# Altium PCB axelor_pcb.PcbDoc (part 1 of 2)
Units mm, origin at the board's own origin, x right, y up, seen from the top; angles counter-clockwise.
Board outline 74.68 x 44.83 mm, 4 copper layers (Top Layer, Int1 (GND), Int2 (PWR), Bottom Layer), stack 1.586 mm thick; 281 components, 64 nets, 713 pads, 300 vias.
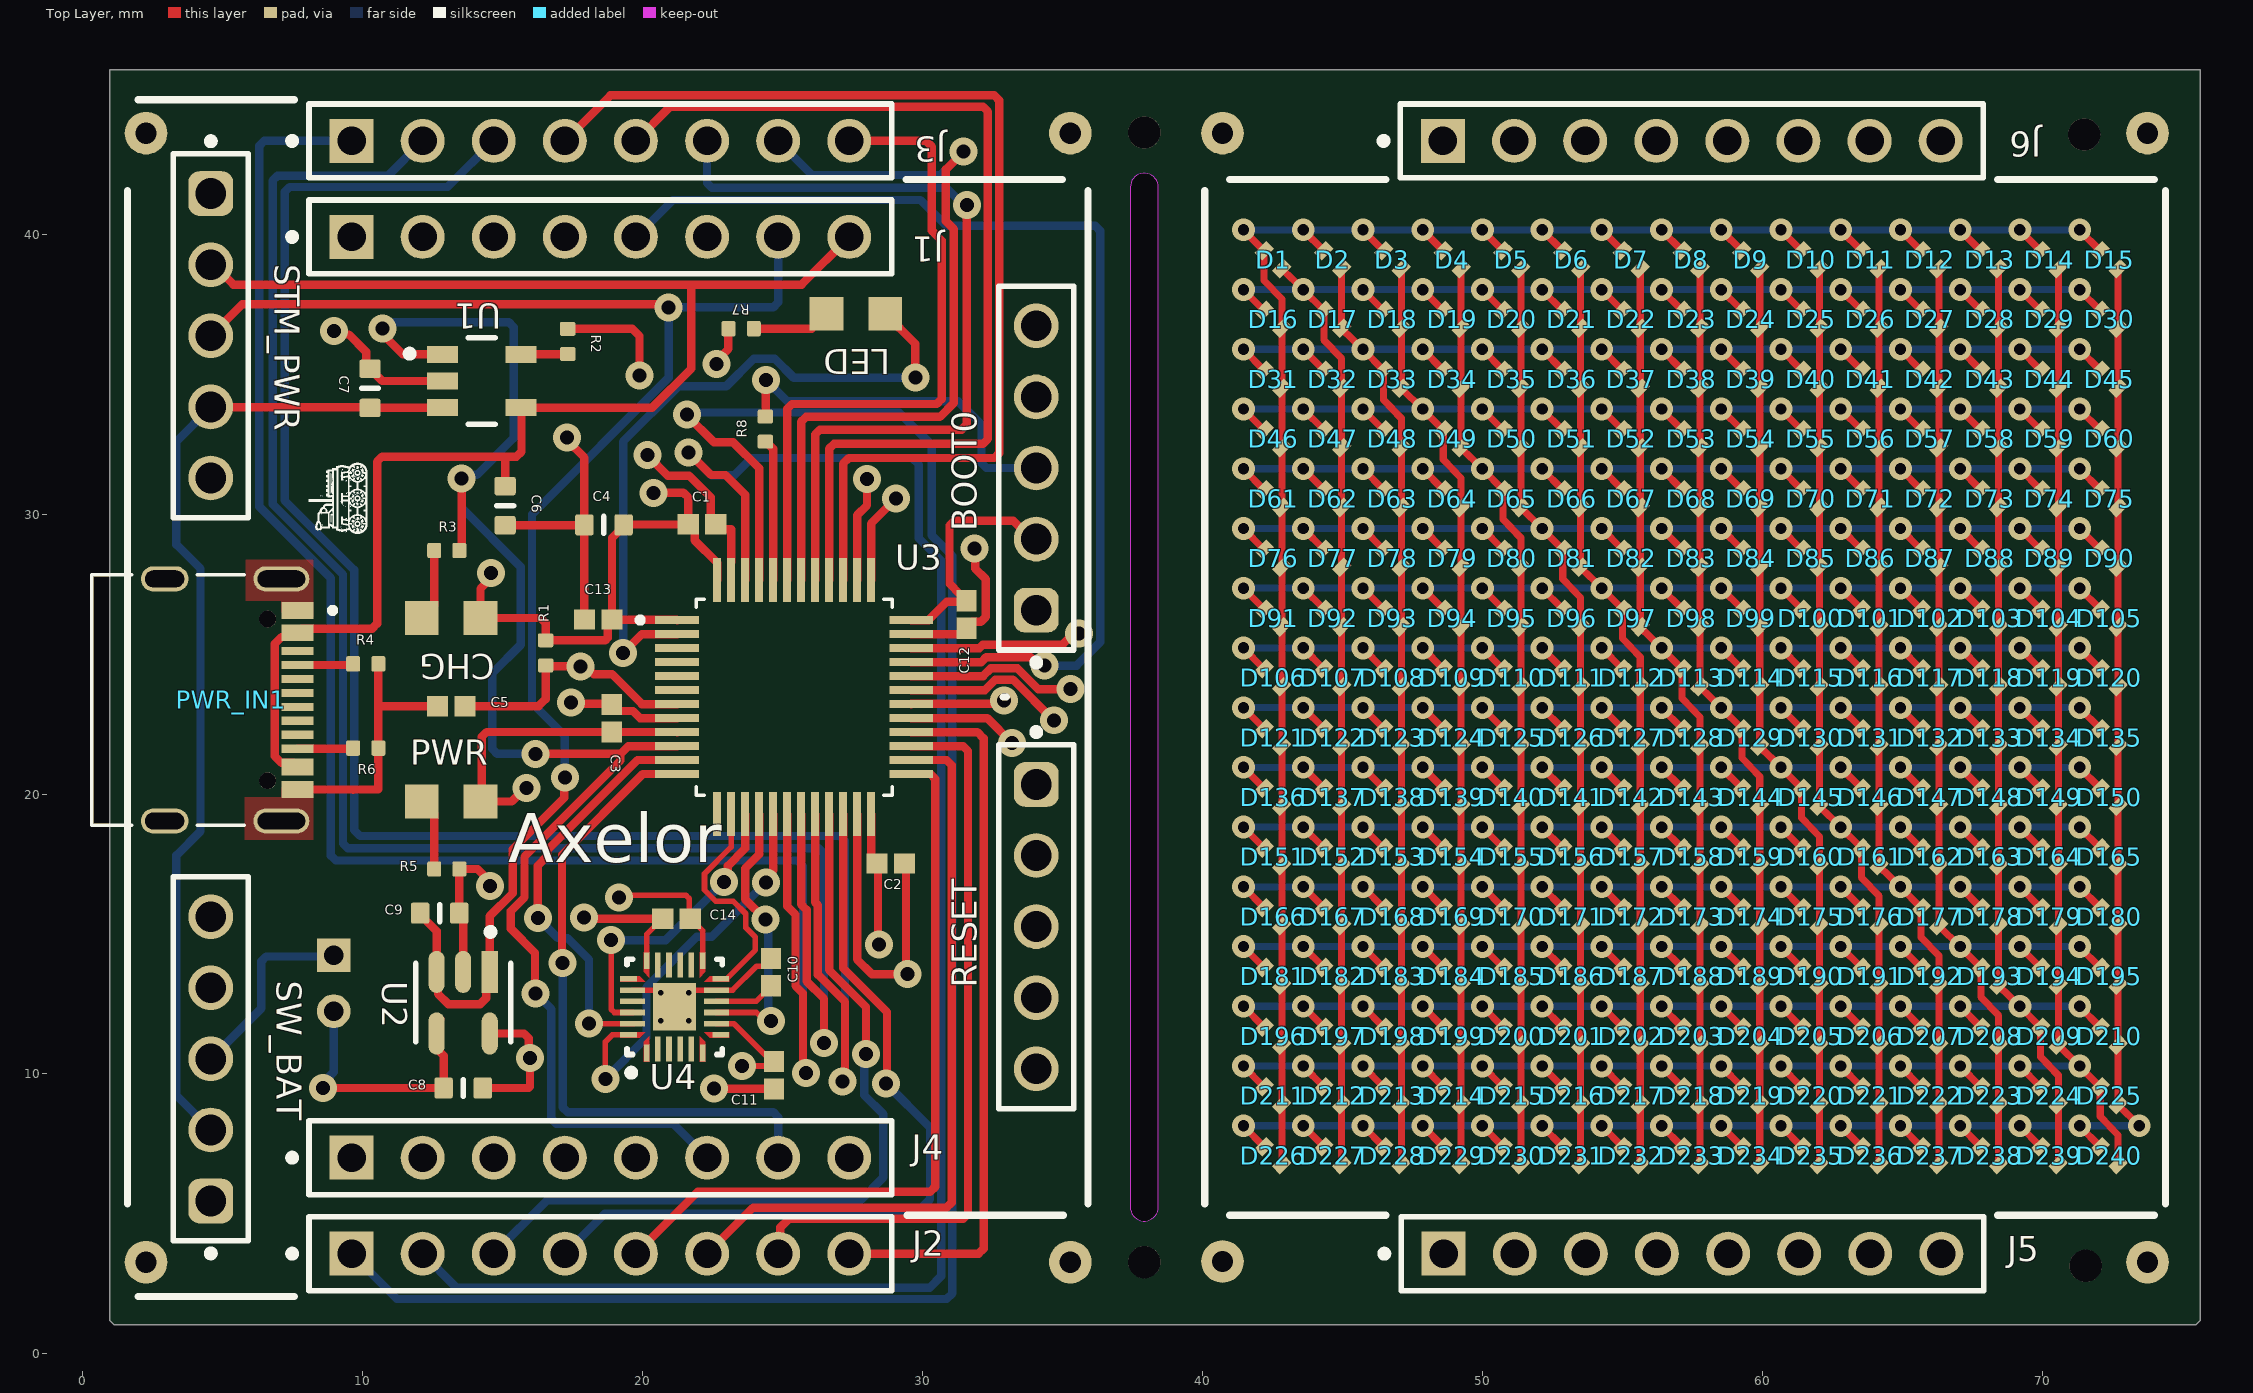
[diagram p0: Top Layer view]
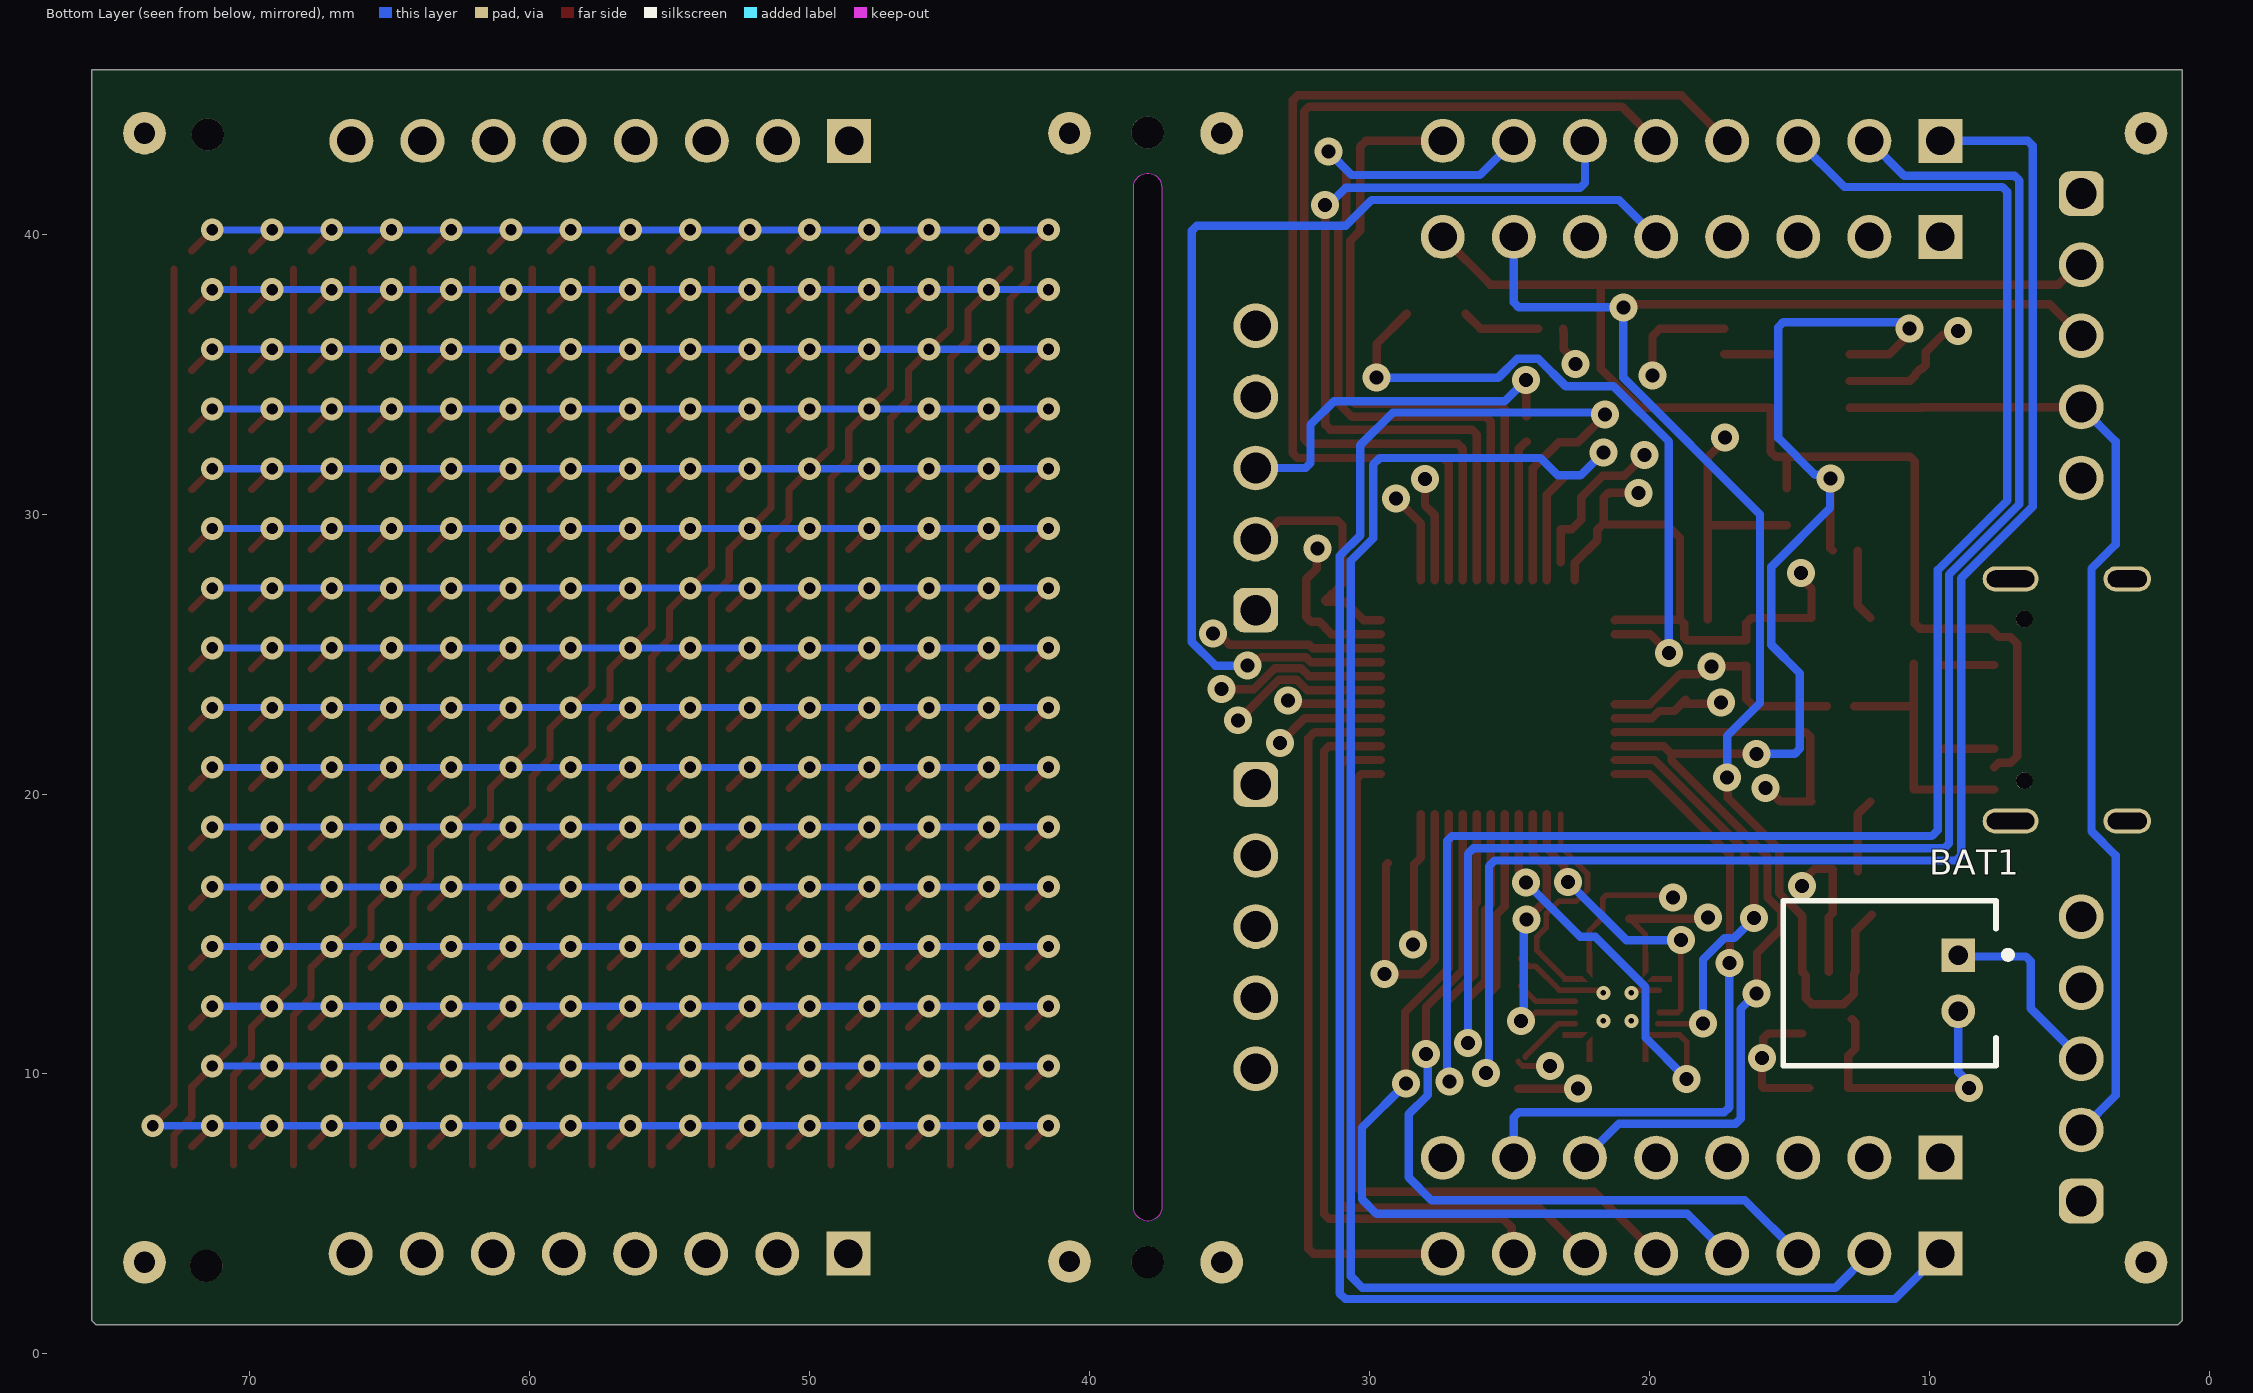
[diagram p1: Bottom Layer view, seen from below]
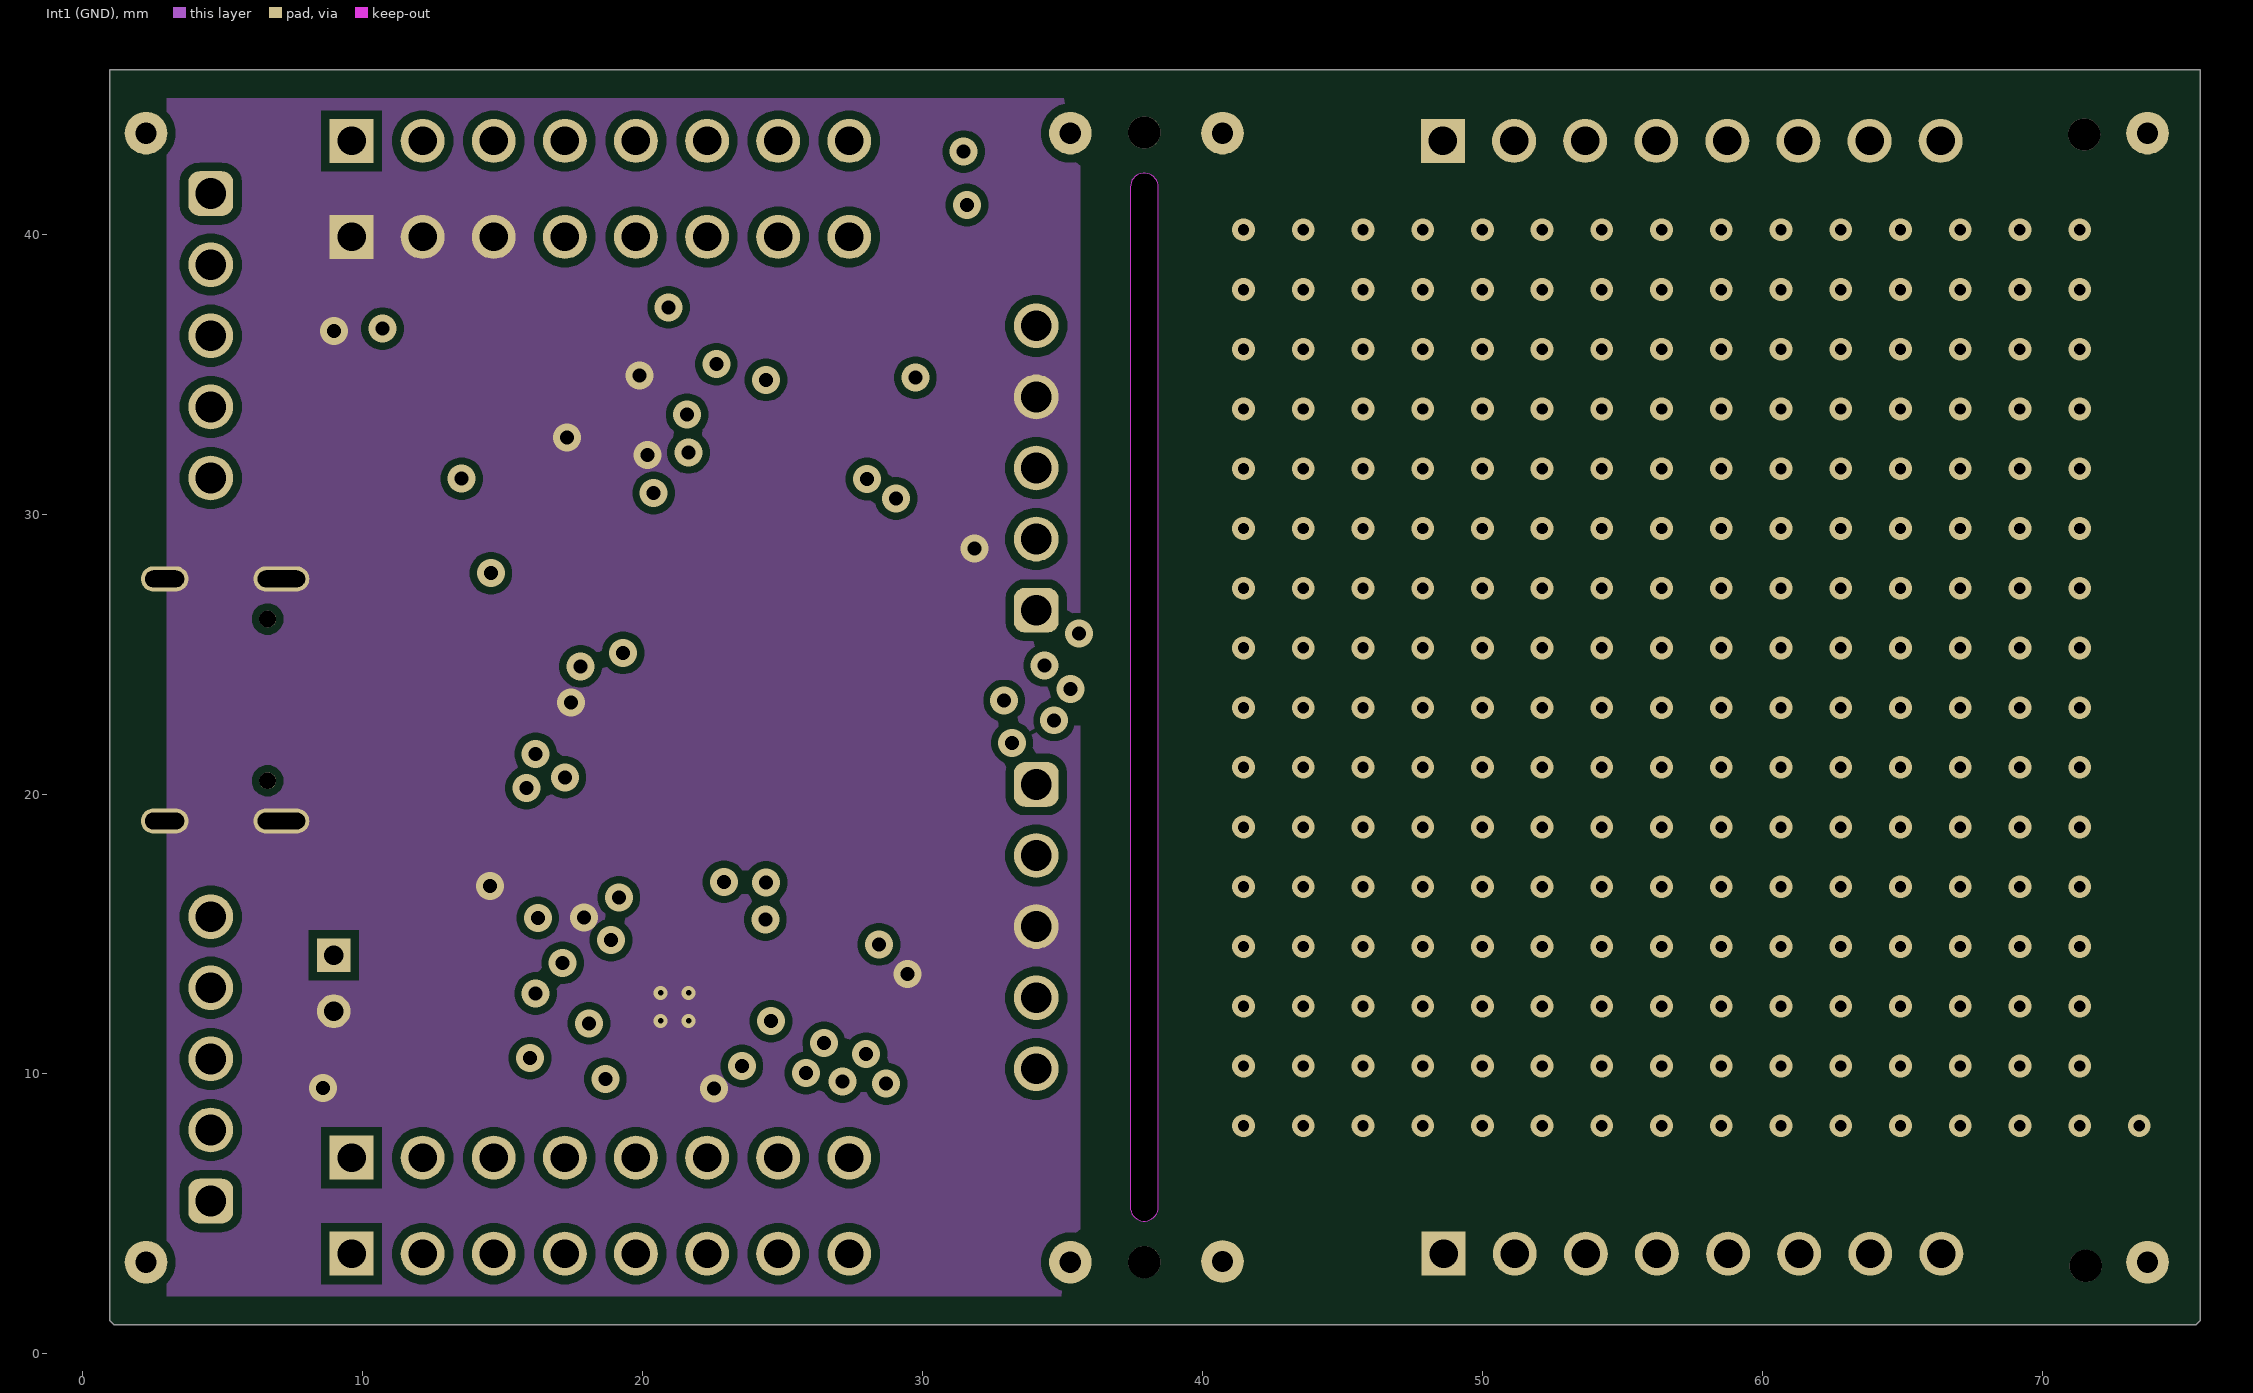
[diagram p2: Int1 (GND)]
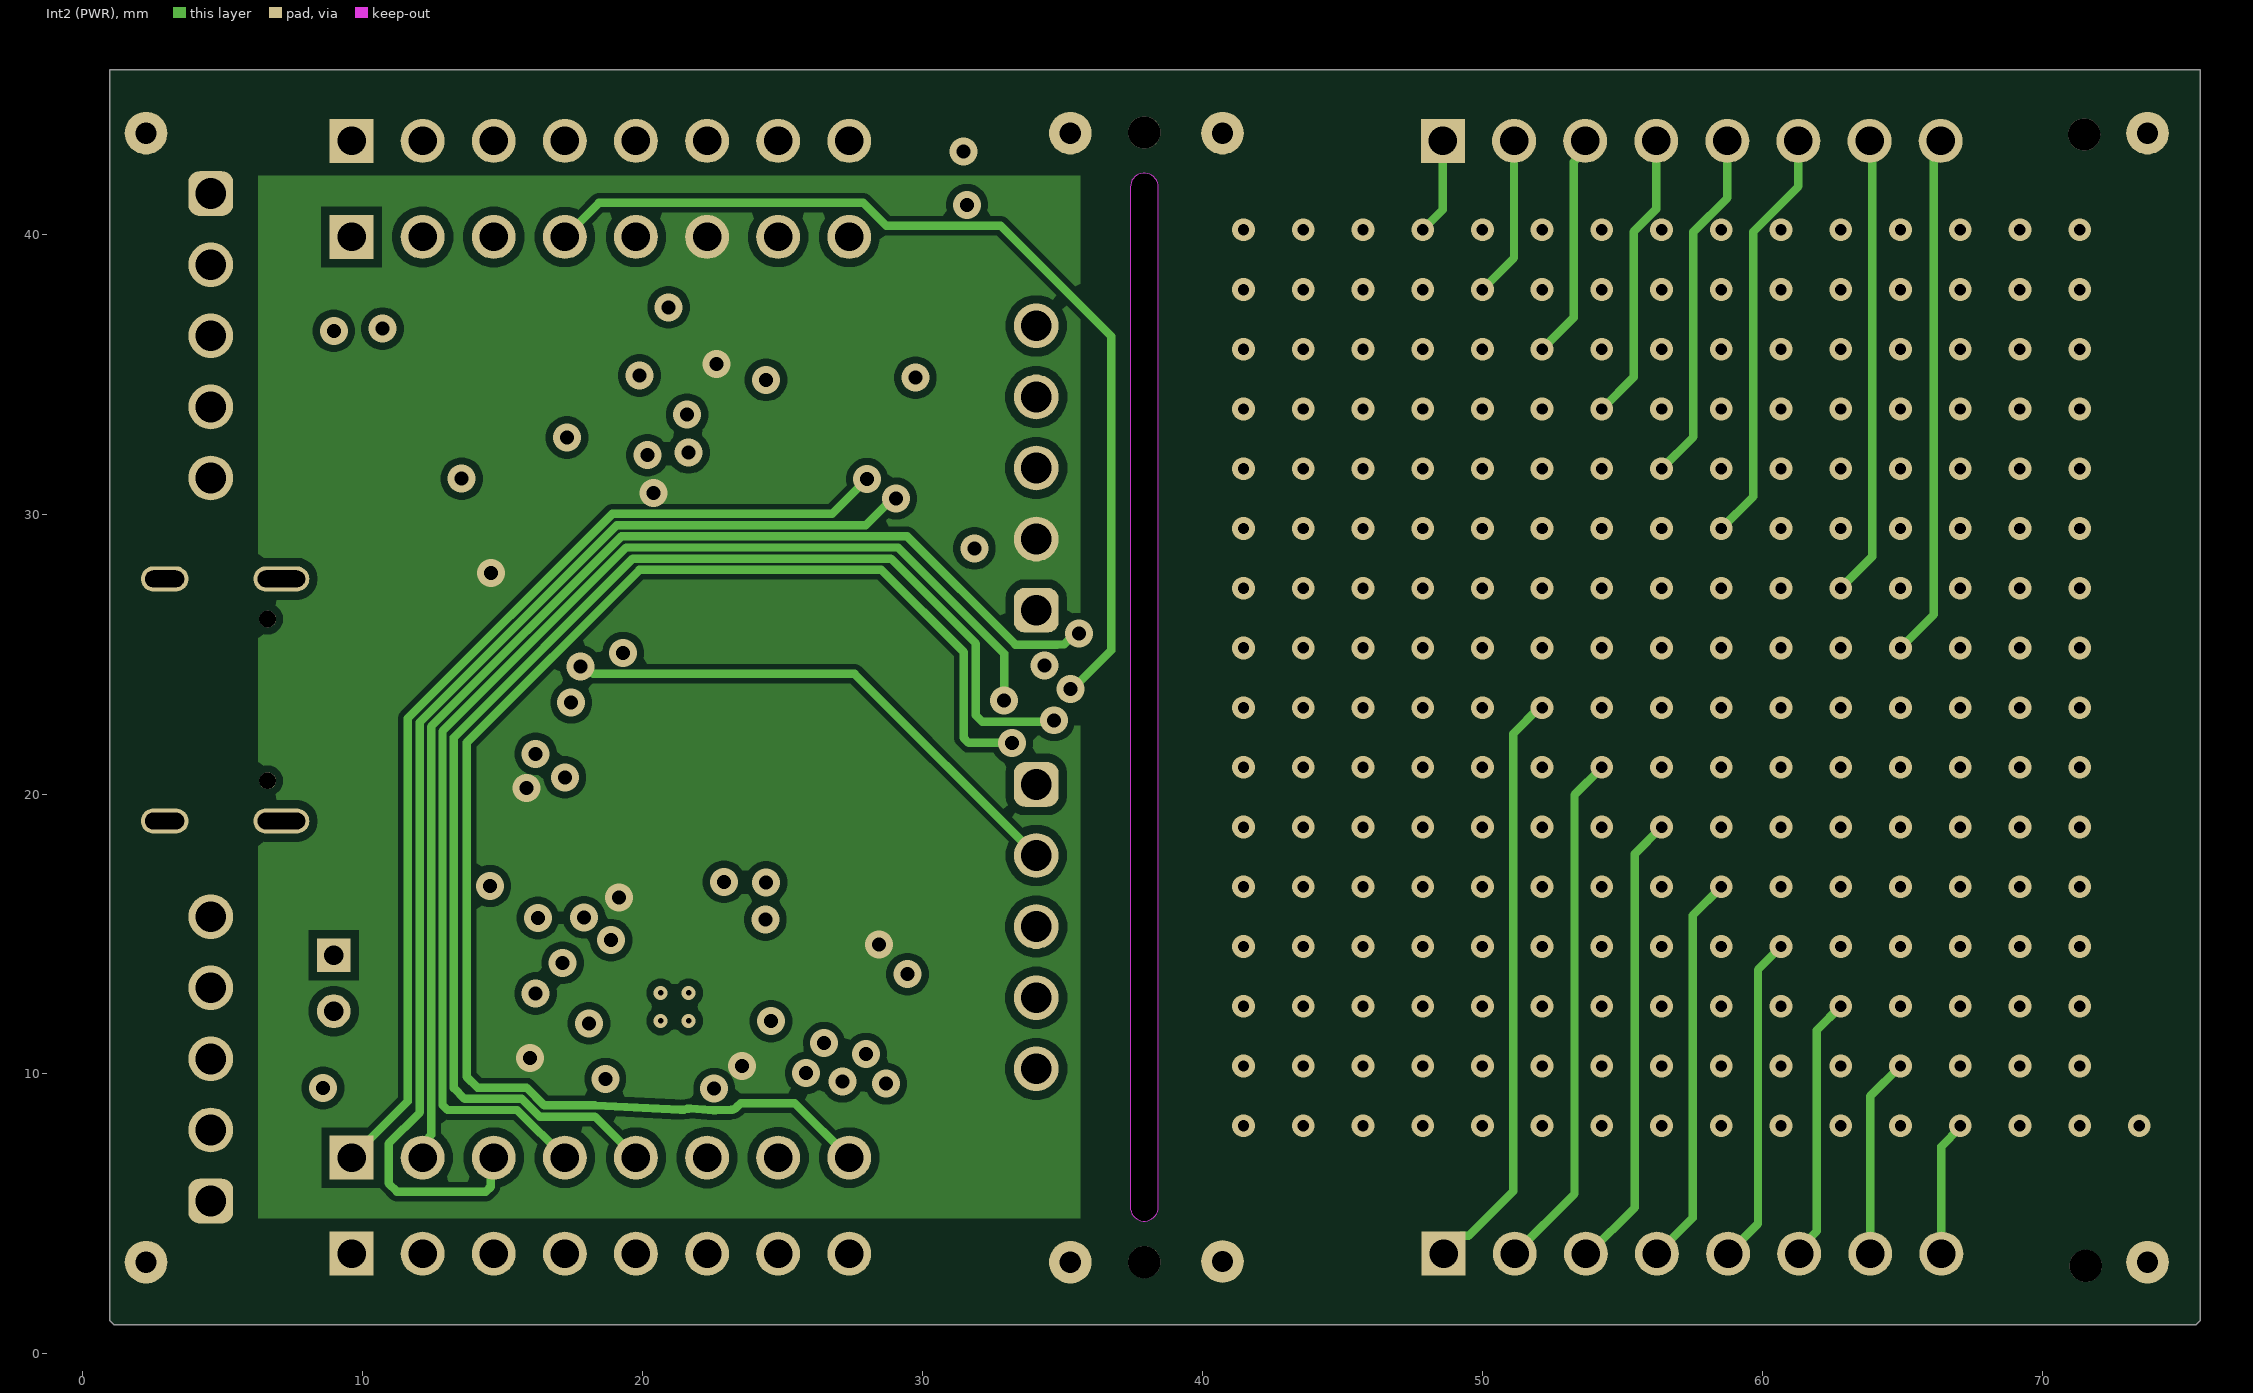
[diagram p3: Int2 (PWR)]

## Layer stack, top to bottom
Top Solder: solder mask 0.0254, SM-001, Dk 4
Top Layer: signal copper 0.035
Dielectric 1: prepreg 0.2104, PP-017, Dk 4.4
Int1 (GND): signal copper 0.0152
Dielectric 3: core 1.065, Core-039, Dk 4.43
Int2 (PWR): signal copper 0.0152
Dielectric 5: prepreg 0.2104, PP-017, Dk 4.4
Bottom Layer: signal copper 0.035
Bottom Solder: solder mask 0.0254, SM-001, Dk 4

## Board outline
0.965,1.19 0.965,45.872 75.641,45.872 75.641,1.19 75.492,1.041 1.114,1.041
cut-out: 37.422,5.243 ccw(c37.922,5.243) 38.422,5.243 38.422,41.681 ccw(c37.922,41.681) 37.422,41.681 37.422,6.51

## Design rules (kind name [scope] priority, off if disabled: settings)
Clearance [All] p1: gap=0.254 ignorepadtopadclearanceinfootprint=FALSE except(0.1: Arc-Arc Arc-Track Arc-SMDPad Arc-Via Track-Track Track-SMDPad Track-Via; 0.15: SMDPad-SMDPad; 0.2: Arc-Fill Arc-Poly Arc-Region Track-Fill Track-Poly Track-Region SMDPad-Fill SMDPad-Poly SMDPad-Region SMDPad-Hole Fill-Fill Fill-Poly Fill-Region Poly-Poly Poly-Region Region-Region; 0.28: Arc-THPad Track-THPad; 0.3: THPad-Fill THPad-Poly THPad-Region)
MinimumSolderMaskSliver [All] p1: minsoldermaskwidth=0.1
PolygonConnect [All] p1: connectstyle=Direct reliefconductorwidth=0.254 reliefentries=4 polygonreliefangle="90 Angle" airgapwidth=0.254
RoutingVias [All] p1: holewidth=0.5 width=1 viastyle="Through Hole" minholewidth=0.15 minwidth=0.25 maxholewidth=0.711 maxwidth=1.27
SolderMaskExpansion [All] p1: expansion=0 istentingtop=FALSE
SupplyNets "Schematic Supply Nets_4" [InNet('VBUS')] p1: voltage=0.000
SupplyNets "Schematic Supply Nets_3" [InNet('VCC3V3')] p2: voltage=0.000
SupplyNets "Schematic Supply Nets_2" [InNet('VBAT')] p3: voltage=0.000
SupplyNets "Schematic Supply Nets_1" [InNet('GND')] p4: voltage=0.000
SupplyNets "Schematic Supply Nets" [InNet('VCC5V')] p5: voltage=0.000
UnRoutedNet [All] p1: checkbadconnections=TRUE
Width [All] p1: maxlimit=1 minlimit=0.2 preferedwidth=0.3
28 further rules are at their usual default settings.

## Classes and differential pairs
component class main_board: BAT1 BOOT0 C1 C2 C3 C4 C5 C6 C7 C8 C9 C10 C11 C12 C13 C14 CHG J1 J2 J3 J4 LED PWR PWR_IN1 R1 R2 R3 R4 R5 R6 R7 R8 RESET STM_PWR SW_BAT U1 U2 U3 U4
component class led_matrix: D1 D2 D3 D4 D5 D6 D7 D8 D9 D10 D11 D12 D13 D14 D15 D16 D17 D18 D19 D20 D21 D22 D23 D24 D25 D26 D27 D28 D29 D30 D31 D32 D33 D34 D35 D36 D37 D38 D39 D40 D41 D42 D43 D44 D45 D46 D47 D48 D49 D50 D51 D52 D53 D54 D55 D56 D57 D58 D59 D60 D61 D62 D63 D64 D65 D66 D67 D68 D69 D70 D71 D72 D73 D74 D75 D76 D77 D78 D79 D80 D81 D82 D83 D84 D85 D86 D87 D88 D89 D90 D91 D92 D93 D94 D95 D96 D97 D98 D99 D100 D101 D102 D103 D104 D105 D106 D107 D108 D109 D110 D111 D112 D113 D114 D115 D116 D117 D118 D119 D120 D121 D122 D123 D124 D125 D126 D127 D128 D129 D130 D131 D132 D133 D134 D135 D136 D137 D138 D139 D140 D141 D142 D143 D144 D145 D146 D147 D148 D149 D150 D151 D152 D153 D154 D155 D156 D157 D158 D159 D160 D161 D162 D163 D164 D165 D166 D167 D168 D169 D170 D171 D172 D173 D174 D175 D176 D177 D178 D179 D180 D181 D182 D183 D184 D185 D186 D187 D188 D189 D190 D191 D192 D193 D194 D195 D196 D197 D198 D199 D200 D201 D202 D203 D204 D205 D206 D207 D208 D209 D210 D211 D212 D213 D214 D215 D216 D217 D218 D219 D220 D221 D222 D223 D224 D225 D226 D227 D228 D229 D230 D231 D232 D233 D234 D235 D236 D237 D238 D239 D240 J5 J6

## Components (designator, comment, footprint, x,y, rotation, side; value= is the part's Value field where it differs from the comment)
BAT1 "S2B-PH-K-S(LF)(SN)" JST-S2B-PH-K-S_V 11.416,13.243 r270 bottom
BOOT0 "61300511121" 61300511121 34.061,31.648 r90 top
C1 "100nF" CAPC1050X55X23ML05T13 22.123,29.642 r180 top
C2 "100nF" CAPC1050X55X23ML05T13 28.862,17.526 r180 top
C3 "100nF" CAPC1050X55X23ML05T13 18.898,22.708 r270 top
C4 "10uF" CAPC0603(1608)100_L 18.618,29.616 r0 top value=4.7µF
C5 "100nF" CAPC1050X55X23ML05T13 13.165,23.139 r0 top
C6 "4u7" CAPC0603(1608)100_L 15.088,30.302 r90 top value=4.7µF
C7 "4u7" CAPC0603(1608)100_L 10.262,34.493 r270 top value=4.7µF
C8 "4u7" CAPC0603(1608)100_L 13.589,9.5 r0 top value=4.7µF
C9 "4u7" CAPC0603(1608)100_L 12.751,15.748 r180 top value=4.7µF
C10 "100nF" CAPC1050X55X23ML05T13 24.587,13.64 r270 top
C11 "100nF" CAPC1050X55X23ML05T13 24.689,9.957 r90 top
C12 "100nF" CAPC1050X55X23ML05T13 31.572,26.416 r90 top
C13 "100nF" CAPC1050X55X23ML05T13 18.415,26.238 r0 top
C14 "100nF" CAPC1050X55X23ML05T13 21.209,15.545 r0 top
CHG "YELLOW_0805" EVRL-17-21SYGC_V 13.157,26.289 r180 top
D1 "LED_MTX" EVRL-0402-2_V 42.52,39.09 r315 top
D2 "LED_MTX" EVRL-0402-2_V 44.654,39.09 r315 top
D3 "LED_MTX" EVRL-0402-2_V 46.787,39.09 r315 top
D4 "LED_MTX" EVRL-0402-2_V 48.921,39.09 r315 top
D5 "LED_MTX" EVRL-0402-2_V 51.055,39.09 r315 top
D6 "LED_MTX" EVRL-0402-2_V 53.188,39.09 r315 top
D7 "LED_MTX" EVRL-0402-2_V 55.322,39.09 r315 top
D8 "LED_MTX" EVRL-0402-2_V 57.455,39.09 r315 top
D9 "LED_MTX" EVRL-0402-2_V 59.589,39.09 r315 top
D10 "LED_MTX" EVRL-0402-2_V 61.723,39.09 r315 top
D11 "LED_MTX" EVRL-0402-2_V 63.856,39.09 r315 top
D12 "LED_MTX" EVRL-0402-2_V 65.99,39.09 r315 top
D13 "LED_MTX" EVRL-0402-2_V 68.123,39.09 r315 top
D14 "LED_MTX" EVRL-0402-2_V 70.257,39.09 r315 top
D15 "LED_MTX" EVRL-0402-2_V 72.391,39.09 r315 top
D16 "LED_MTX" EVRL-0402-2_V 42.52,36.956 r315 top
D17 "LED_MTX" EVRL-0402-2_V 44.654,36.956 r315 top
D18 "LED_MTX" EVRL-0402-2_V 46.787,36.956 r315 top
D19 "LED_MTX" EVRL-0402-2_V 48.921,36.956 r315 top
D20 "LED_MTX" EVRL-0402-2_V 51.055,36.956 r315 top
D21 "LED_MTX" EVRL-0402-2_V 53.188,36.956 r315 top
D22 "LED_MTX" EVRL-0402-2_V 55.322,36.956 r315 top
D23 "LED_MTX" EVRL-0402-2_V 57.455,36.956 r315 top
D24 "LED_MTX" EVRL-0402-2_V 59.589,36.956 r315 top
D25 "LED_MTX" EVRL-0402-2_V 61.723,36.956 r315 top
D26 "LED_MTX" EVRL-0402-2_V 63.856,36.956 r315 top
D27 "LED_MTX" EVRL-0402-2_V 65.99,36.956 r315 top
D28 "LED_MTX" EVRL-0402-2_V 68.123,36.956 r315 top
D29 "LED_MTX" EVRL-0402-2_V 70.257,36.956 r315 top
D30 "LED_MTX" EVRL-0402-2_V 72.391,36.956 r315 top
D31 "LED_MTX" EVRL-0402-2_V 42.52,34.823 r315 top
D32 "LED_MTX" EVRL-0402-2_V 44.654,34.823 r315 top
D33 "LED_MTX" EVRL-0402-2_V 46.787,34.823 r315 top
D34 "LED_MTX" EVRL-0402-2_V 48.921,34.823 r315 top
D35 "LED_MTX" EVRL-0402-2_V 51.055,34.823 r315 top
D36 "LED_MTX" EVRL-0402-2_V 53.188,34.823 r315 top
D37 "LED_MTX" EVRL-0402-2_V 55.322,34.823 r315 top
D38 "LED_MTX" EVRL-0402-2_V 57.455,34.823 r315 top
D39 "LED_MTX" EVRL-0402-2_V 59.589,34.823 r315 top
D40 "LED_MTX" EVRL-0402-2_V 61.723,34.823 r315 top
D41 "LED_MTX" EVRL-0402-2_V 63.856,34.823 r315 top
D42 "LED_MTX" EVRL-0402-2_V 65.99,34.823 r315 top
D43 "LED_MTX" EVRL-0402-2_V 68.123,34.823 r315 top
D44 "LED_MTX" EVRL-0402-2_V 70.257,34.823 r315 top
D45 "LED_MTX" EVRL-0402-2_V 72.391,34.823 r315 top
D46 "LED_MTX" EVRL-0402-2_V 42.52,32.689 r315 top
D47 "LED_MTX" EVRL-0402-2_V 44.654,32.689 r315 top
D48 "LED_MTX" EVRL-0402-2_V 46.787,32.689 r315 top
D49 "LED_MTX" EVRL-0402-2_V 48.921,32.689 r315 top
D50 "LED_MTX" EVRL-0402-2_V 51.055,32.689 r315 top
D51 "LED_MTX" EVRL-0402-2_V 53.188,32.689 r315 top
D52 "LED_MTX" EVRL-0402-2_V 55.322,32.689 r315 top
D53 "LED_MTX" EVRL-0402-2_V 57.455,32.689 r315 top
D54 "LED_MTX" EVRL-0402-2_V 59.589,32.689 r315 top
D55 "LED_MTX" EVRL-0402-2_V 61.723,32.689 r315 top
D56 "LED_MTX" EVRL-0402-2_V 63.856,32.689 r315 top
D57 "LED_MTX" EVRL-0402-2_V 65.99,32.689 r315 top
D58 "LED_MTX" EVRL-0402-2_V 68.123,32.689 r315 top
D59 "LED_MTX" EVRL-0402-2_V 70.257,32.689 r315 top
D60 "LED_MTX" EVRL-0402-2_V 72.391,32.689 r315 top
D61 "LED_MTX" EVRL-0402-2_V 42.52,30.556 r315 top
D62 "LED_MTX" EVRL-0402-2_V 44.654,30.556 r315 top
D63 "LED_MTX" EVRL-0402-2_V 46.787,30.556 r315 top
D64 "LED_MTX" EVRL-0402-2_V 48.921,30.556 r315 top
D65 "LED_MTX" EVRL-0402-2_V 51.055,30.556 r315 top
D66 "LED_MTX" EVRL-0402-2_V 53.188,30.556 r315 top
D67 "LED_MTX" EVRL-0402-2_V 55.322,30.556 r315 top
D68 "LED_MTX" EVRL-0402-2_V 57.455,30.556 r315 top
D69 "LED_MTX" EVRL-0402-2_V 59.589,30.556 r315 top
D70 "LED_MTX" EVRL-0402-2_V 61.723,30.556 r315 top
D71 "LED_MTX" EVRL-0402-2_V 63.856,30.556 r315 top
D72 "LED_MTX" EVRL-0402-2_V 65.99,30.556 r315 top
D73 "LED_MTX" EVRL-0402-2_V 68.123,30.556 r315 top
D74 "LED_MTX" EVRL-0402-2_V 70.257,30.556 r315 top
D75 "LED_MTX" EVRL-0402-2_V 72.391,30.556 r315 top
D76 "LED_MTX" EVRL-0402-2_V 42.52,28.422 r315 top
D77 "LED_MTX" EVRL-0402-2_V 44.654,28.422 r315 top
D78 "LED_MTX" EVRL-0402-2_V 46.787,28.422 r315 top
D79 "LED_MTX" EVRL-0402-2_V 48.921,28.422 r315 top
D80 "LED_MTX" EVRL-0402-2_V 51.055,28.422 r315 top
D81 "LED_MTX" EVRL-0402-2_V 53.188,28.422 r315 top
D82 "LED_MTX" EVRL-0402-2_V 55.322,28.422 r315 top
D83 "LED_MTX" EVRL-0402-2_V 57.455,28.422 r315 top
D84 "LED_MTX" EVRL-0402-2_V 59.589,28.422 r315 top
D85 "LED_MTX" EVRL-0402-2_V 61.723,28.422 r315 top
D86 "LED_MTX" EVRL-0402-2_V 63.856,28.422 r315 top
D87 "LED_MTX" EVRL-0402-2_V 65.99,28.422 r315 top
D88 "LED_MTX" EVRL-0402-2_V 68.123,28.422 r315 top
D89 "LED_MTX" EVRL-0402-2_V 70.257,28.422 r315 top
D90 "LED_MTX" EVRL-0402-2_V 72.391,28.422 r315 top
D91 "LED_MTX" EVRL-0402-2_V 42.52,26.288 r315 top
D92 "LED_MTX" EVRL-0402-2_V 44.654,26.288 r315 top
D93 "LED_MTX" EVRL-0402-2_V 46.787,26.288 r315 top
D94 "LED_MTX" EVRL-0402-2_V 48.921,26.288 r315 top
D95 "LED_MTX" EVRL-0402-2_V 51.055,26.288 r315 top
D96 "LED_MTX" EVRL-0402-2_V 53.188,26.288 r315 top
D97 "LED_MTX" EVRL-0402-2_V 55.322,26.288 r315 top
D98 "LED_MTX" EVRL-0402-2_V 57.455,26.288 r315 top
D99 "LED_MTX" EVRL-0402-2_V 59.589,26.288 r315 top
D100 "LED_MTX" EVRL-0402-2_V 61.723,26.288 r315 top
D101 "LED_MTX" EVRL-0402-2_V 63.856,26.288 r315 top
D102 "LED_MTX" EVRL-0402-2_V 65.99,26.288 r315 top
D103 "LED_MTX" EVRL-0402-2_V 68.123,26.288 r315 top
D104 "LED_MTX" EVRL-0402-2_V 70.257,26.288 r315 top
D105 "LED_MTX" EVRL-0402-2_V 72.391,26.288 r315 top
D106 "LED_MTX" EVRL-0402-2_V 42.52,24.155 r315 top
D107 "LED_MTX" EVRL-0402-2_V 44.654,24.155 r315 top
D108 "LED_MTX" EVRL-0402-2_V 46.787,24.155 r315 top
D109 "LED_MTX" EVRL-0402-2_V 48.921,24.155 r315 top
D110 "LED_MTX" EVRL-0402-2_V 51.055,24.155 r315 top
D111 "LED_MTX" EVRL-0402-2_V 53.188,24.155 r315 top
D112 "LED_MTX" EVRL-0402-2_V 55.322,24.155 r315 top
D113 "LED_MTX" EVRL-0402-2_V 57.455,24.155 r315 top
D114 "LED_MTX" EVRL-0402-2_V 59.589,24.155 r315 top
D115 "LED_MTX" EVRL-0402-2_V 61.723,24.155 r315 top
D116 "LED_MTX" EVRL-0402-2_V 63.856,24.155 r315 top
D117 "LED_MTX" EVRL-0402-2_V 65.99,24.155 r315 top
D118 "LED_MTX" EVRL-0402-2_V 68.123,24.155 r315 top
D119 "LED_MTX" EVRL-0402-2_V 70.257,24.155 r315 top
D120 "LED_MTX" EVRL-0402-2_V 72.391,24.155 r315 top
D121 "LED_MTX" EVRL-0402-2_V 42.52,22.021 r315 top
D122 "LED_MTX" EVRL-0402-2_V 44.654,22.021 r315 top
D123 "LED_MTX" EVRL-0402-2_V 46.787,22.021 r315 top
D124 "LED_MTX" EVRL-0402-2_V 48.921,22.021 r315 top
D125 "LED_MTX" EVRL-0402-2_V 51.055,22.021 r315 top
D126 "LED_MTX" EVRL-0402-2_V 53.188,22.021 r315 top
D127 "LED_MTX" EVRL-0402-2_V 55.322,22.021 r315 top
D128 "LED_MTX" EVRL-0402-2_V 57.455,22.021 r315 top
D129 "LED_MTX" EVRL-0402-2_V 59.589,22.021 r315 top
D130 "LED_MTX" EVRL-0402-2_V 61.723,22.021 r315 top
D131 "LED_MTX" EVRL-0402-2_V 63.856,22.021 r315 top
D132 "LED_MTX" EVRL-0402-2_V 65.99,22.021 r315 top
D133 "LED_MTX" EVRL-0402-2_V 68.123,22.021 r315 top
D134 "LED_MTX" EVRL-0402-2_V 70.257,22.021 r315 top
D135 "LED_MTX" EVRL-0402-2_V 72.391,22.021 r315 top
D136 "LED_MTX" EVRL-0402-2_V 42.52,19.888 r315 top
D137 "LED_MTX" EVRL-0402-2_V 44.654,19.888 r315 top
D138 "LED_MTX" EVRL-0402-2_V 46.787,19.888 r315 top
D139 "LED_MTX" EVRL-0402-2_V 48.921,19.888 r315 top
D140 "LED_MTX" EVRL-0402-2_V 51.055,19.888 r315 top
D141 "LED_MTX" EVRL-0402-2_V 53.188,19.888 r315 top
D142 "LED_MTX" EVRL-0402-2_V 55.322,19.888 r315 top
D143 "LED_MTX" EVRL-0402-2_V 57.455,19.888 r315 top
D144 "LED_MTX" EVRL-0402-2_V 59.589,19.888 r315 top
D145 "LED_MTX" EVRL-0402-2_V 61.723,19.888 r315 top
D146 "LED_MTX" EVRL-0402-2_V 63.856,19.888 r315 top
D147 "LED_MTX" EVRL-0402-2_V 65.99,19.888 r315 top
D148 "LED_MTX" EVRL-0402-2_V 68.123,19.888 r315 top
D149 "LED_MTX" EVRL-0402-2_V 70.257,19.888 r315 top
D150 "LED_MTX" EVRL-0402-2_V 72.391,19.888 r315 top
D151 "LED_MTX" EVRL-0402-2_V 42.52,17.754 r315 top
D152 "LED_MTX" EVRL-0402-2_V 44.654,17.754 r315 top
D153 "LED_MTX" EVRL-0402-2_V 46.787,17.754 r315 top
D154 "LED_MTX" EVRL-0402-2_V 48.921,17.754 r315 top
D155 "LED_MTX" EVRL-0402-2_V 51.055,17.754 r315 top
D156 "LED_MTX" EVRL-0402-2_V 53.188,17.754 r315 top
D157 "LED_MTX" EVRL-0402-2_V 55.322,17.754 r315 top
D158 "LED_MTX" EVRL-0402-2_V 57.455,17.754 r315 top
D159 "LED_MTX" EVRL-0402-2_V 59.589,17.754 r315 top
D160 "LED_MTX" EVRL-0402-2_V 61.723,17.754 r315 top
D161 "LED_MTX" EVRL-0402-2_V 63.856,17.754 r315 top
D162 "LED_MTX" EVRL-0402-2_V 65.99,17.754 r315 top
D163 "LED_MTX" EVRL-0402-2_V 68.123,17.754 r315 top
D164 "LED_MTX" EVRL-0402-2_V 70.257,17.754 r315 top
D165 "LED_MTX" EVRL-0402-2_V 72.391,17.754 r315 top
D166 "LED_MTX" EVRL-0402-2_V 42.52,15.62 r315 top
D167 "LED_MTX" EVRL-0402-2_V 44.654,15.62 r315 top
D168 "LED_MTX" EVRL-0402-2_V 46.787,15.62 r315 top
D169 "LED_MTX" EVRL-0402-2_V 48.921,15.62 r315 top
D170 "LED_MTX" EVRL-0402-2_V 51.055,15.62 r315 top
D171 "LED_MTX" EVRL-0402-2_V 53.188,15.62 r315 top
D172 "LED_MTX" EVRL-0402-2_V 55.322,15.62 r315 top
D173 "LED_MTX" EVRL-0402-2_V 57.455,15.62 r315 top
D174 "LED_MTX" EVRL-0402-2_V 59.589,15.62 r315 top
D175 "LED_MTX" EVRL-0402-2_V 61.723,15.62 r315 top
D176 "LED_MTX" EVRL-0402-2_V 63.856,15.62 r315 top
D177 "LED_MTX" EVRL-0402-2_V 65.99,15.62 r315 top
D178 "LED_MTX" EVRL-0402-2_V 68.123,15.62 r315 top
D179 "LED_MTX" EVRL-0402-2_V 70.257,15.62 r315 top
D180 "LED_MTX" EVRL-0402-2_V 72.391,15.62 r315 top
D181 "LED_MTX" EVRL-0402-2_V 42.52,13.487 r315 top
D182 "LED_MTX" EVRL-0402-2_V 44.654,13.487 r315 top
D183 "LED_MTX" EVRL-0402-2_V 46.787,13.487 r315 top
D184 "LED_MTX" EVRL-0402-2_V 48.921,13.487 r315 top
D185 "LED_MTX" EVRL-0402-2_V 51.055,13.487 r315 top
D186 "LED_MTX" EVRL-0402-2_V 53.188,13.487 r315 top
D187 "LED_MTX" EVRL-0402-2_V 55.322,13.487 r315 top
D188 "LED_MTX" EVRL-0402-2_V 57.455,13.487 r315 top
D189 "LED_MTX" EVRL-0402-2_V 59.589,13.487 r315 top
D190 "LED_MTX" EVRL-0402-2_V 61.723,13.487 r315 top
D191 "LED_MTX" EVRL-0402-2_V 63.856,13.487 r315 top
D192 "LED_MTX" EVRL-0402-2_V 65.99,13.487 r315 top
D193 "LED_MTX" EVRL-0402-2_V 68.123,13.487 r315 top
D194 "LED_MTX" EVRL-0402-2_V 70.257,13.487 r315 top
D195 "LED_MTX" EVRL-0402-2_V 72.391,13.487 r315 top
D196 "LED_MTX" EVRL-0402-2_V 42.52,11.353 r315 top
D197 "LED_MTX" EVRL-0402-2_V 44.654,11.353 r315 top
D198 "LED_MTX" EVRL-0402-2_V 46.787,11.353 r315 top
D199 "LED_MTX" EVRL-0402-2_V 48.921,11.353 r315 top
D200 "LED_MTX" EVRL-0402-2_V 51.055,11.353 r315 top
D201 "LED_MTX" EVRL-0402-2_V 53.188,11.353 r315 top
D202 "LED_MTX" EVRL-0402-2_V 55.322,11.353 r315 top
D203 "LED_MTX" EVRL-0402-2_V 57.455,11.353 r315 top
D204 "LED_MTX" EVRL-0402-2_V 59.589,11.353 r315 top
D205 "LED_MTX" EVRL-0402-2_V 61.723,11.353 r315 top
D206 "LED_MTX" EVRL-0402-2_V 63.856,11.353 r315 top
D207 "LED_MTX" EVRL-0402-2_V 65.99,11.353 r315 top
D208 "LED_MTX" EVRL-0402-2_V 68.123,11.353 r315 top
D209 "LED_MTX" EVRL-0402-2_V 70.257,11.353 r315 top
D210 "LED_MTX" EVRL-0402-2_V 72.391,11.353 r315 top
D211 "LED_MTX" EVRL-0402-2_V 42.52,9.22 r315 top
D212 "LED_MTX" EVRL-0402-2_V 44.654,9.22 r315 top
D213 "LED_MTX" EVRL-0402-2_V 46.787,9.22 r315 top
D214 "LED_MTX" EVRL-0402-2_V 48.921,9.22 r315 top
D215 "LED_MTX" EVRL-0402-2_V 51.055,9.22 r315 top
D216 "LED_MTX" EVRL-0402-2_V 53.188,9.22 r315 top
D217 "LED_MTX" EVRL-0402-2_V 55.322,9.22 r315 top
D218 "LED_MTX" EVRL-0402-2_V 57.455,9.22 r315 top
D219 "LED_MTX" EVRL-0402-2_V 59.589,9.22 r315 top
D220 "LED_MTX" EVRL-0402-2_V 61.723,9.22 r315 top
D221 "LED_MTX" EVRL-0402-2_V 63.856,9.22 r315 top
D222 "LED_MTX" EVRL-0402-2_V 65.99,9.22 r315 top
D223 "LED_MTX" EVRL-0402-2_V 68.123,9.22 r315 top
D224 "LED_MTX" EVRL-0402-2_V 70.257,9.22 r315 top
D225 "LED_MTX" EVRL-0402-2_V 72.391,9.22 r315 top
D226 "LED_MTX" EVRL-0402-2_V 42.52,7.086 r315 top
D227 "LED_MTX" EVRL-0402-2_V 44.654,7.086 r315 top
D228 "LED_MTX" EVRL-0402-2_V 46.787,7.086 r315 top
D229 "LED_MTX" EVRL-0402-2_V 48.921,7.086 r315 top
D230 "LED_MTX" EVRL-0402-2_V 51.055,7.086 r315 top
D231 "LED_MTX" EVRL-0402-2_V 53.188,7.086 r315 top
D232 "LED_MTX" EVRL-0402-2_V 55.322,7.086 r315 top
D233 "LED_MTX" EVRL-0402-2_V 57.455,7.086 r315 top
D234 "LED_MTX" EVRL-0402-2_V 59.589,7.086 r315 top
D235 "LED_MTX" EVRL-0402-2_V 61.723,7.086 r315 top
D236 "LED_MTX" EVRL-0402-2_V 63.856,7.086 r315 top
D237 "LED_MTX" EVRL-0402-2_V 65.99,7.086 r315 top
D238 "LED_MTX" EVRL-0402-2_V 68.123,7.086 r315 top
D239 "LED_MTX" EVRL-0402-2_V 70.257,7.086 r315 top
D240 "LED_MTX" EVRL-0402-2_V 72.391,7.086 r315 top
J1 "M20-9990846" FP-M20-9990846-MFG 18.491,39.903 r0 top
J2 "M20-9990846" FP-M20-9990846-MFG 18.491,3.581 r0 top
J3 "M20-9990846" FP-M20-9990846-MFG 18.491,43.332 r0 top
J4 "M20-9990846" FP-M20-9990846-MFG 18.491,7.01 r0 top
J5 "M20-9990846" FP-M20-9990846-MFG 57.506,3.581 r0 top
J6 "M20-9990846" FP-M20-9990846-MFG 57.48,43.332 r0 top
LED "RED_0805" EVRL-17-21SYGC_V 27.618,37.16 r0 top
PWR "GREEN_0805" EVRL-17-21SYGC_V 13.157,19.736 r180 top
PWR_IN1 "TYPE-C-31-M-12" HRO_TYPE-C-31-M-12 2.924,23.362 r270 top
R1 "12k" RESC0402(1005)_L 16.535,25.044 r90 top value=6.2k
R2 "2k" RESC0402(1005)_L 17.323,36.17 r270 top value=6.2k
R3 "1k5" RESC0402(1005)_L 13.005,28.702 r180 top value=6.2k
R4 "5k1" RESC0402(1005)_L 10.109,24.653 r180 top value=6.2k
R5 "1k5" RESC0402(1005)_L 13.005,17.323 r180 top value=6.2k
R6 "5k1" RESC0402(1005)_L 10.109,21.643 r180 top value=6.2k
R7 "1k5" RESC0402(1005)_L 23.52,36.627 r180 top value=6.2k
R8 "12k" RESC0402(1005)_L 24.384,33.038 r270 top value=6.2k
RESET "61300511121" 61300511121 34.061,15.265 r270 top
STM_PWR "61300511121" 61300511121 4.572,36.373 r270 top
SW_BAT "61300511121" 61300511121 4.572,10.541 r90 top
U1 "MCP73832T-2ACI/OT" FP-C04-091-OT-MFG 14.252,34.757 r0 top
U2 "TPS7A0233PDBVR" FP-DBV0005A-IPC_B 13.589,12.548 r270 top
U3 "STM32L431CCT6" QFP50P900X900X160-48N 25.411,23.466 r0 top
U4 "MPU-6500" INSE-MPU-6500-QFN24_M 21.143,12.396 r90 top

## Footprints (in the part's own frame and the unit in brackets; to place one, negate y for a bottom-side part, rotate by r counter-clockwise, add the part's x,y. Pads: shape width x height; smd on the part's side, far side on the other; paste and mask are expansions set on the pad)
61300511121 [mm] "Pin Header, pitch 2.54 mm, THT, Vertical, single row, 5p"
  rrect50% 1.6x1.6 hole 1.1: 1(-5.08,0)
  round 1.6 hole 1.1: 2(-2.54,0) 3(0,0) 4(2.54,0) 5(5.08,0)
  silkscreen extent -7.07,-1.35 6.5,1.35, body extent -6.35,-1.27 6.35,1.27, height 8.57
CAPC0603(1608)100_L [mm] "Chip Capacitor, Body 1.6x0.8mm, Height 1.0mm, IPC High Density"
  rrect25% 0.66x0.76 smd: 1(-0.7,0) 2(0.7,0)
  silkscreen extent 0,-0.3 0,0.3, body extent -0.8,-0.4 0.8,0.4, height 0.95
CAPC1050X55X23ML05T13 [mm] "Chip Capacitor, 2-Leads, Body 1.05x0.55mm, IPC Low Density"
  rect 0.76x0.72 smd: 1(-0.49,0) 2(0.49,0)
  body extent -0.53,-0.28 0.53,0.27, height 0.55
EVRL-17-21SYGC_V [mm] "SMD, 2-Leads, Body 2x1.25mm"
  rect 1.2x1.2 smd: 1(-1.05,0) 2(1.05,0)
  body extent -1,-0.63 1,0.63, height 1.3
EVRL-0402-2_V [mm] "SMD, 2-Leads, Body 1x0.5mm"
  rect 0.4x0.6 smd: 1(-0.45,0) 2(0.45,0)
  body extent -0.5,-0.25 0.5,0.25, height 0.25
FP-C04-091-OT-MFG [mm]
  rect 1.1x0.6 smd paste+0 mask+0: 1(-1.4,0.95) 2(-1.4,0) 3(-1.4,-0.95) 4(1.4,-0.95) 5(1.4,0.95)
  silkscreen extent -2.7,-1.55 0.48,1.55, body extent -2.05,-1.9 2.05,1.9, height 0.25
FP-DBV0005A-IPC_B [mm]
  rect 1.505x0.572 smd paste+0 mask+0: 1(-1.1,0.95)
  rrect100% 1.505x0.572 smd paste+0 mask+0: 2(-1.1,0) 3(-1.1,-0.95) 4(1.1,-0.95) 5(1.1,0.95)
  silkscreen extent -2.65,-1.7 1.4,1.7, body extent -2.1,-1.7 2.1,1.7, height 0.25
FP-M20-9990846-MFG [mm]
  rect 1.57x1.57 hole 1.02 paste-2539.97 mask+0: 1(-8.89,0)
  round 1.57 hole 1.02 paste-2539.97 mask+0: 2(-6.35,0) 3(-3.81,0) 4(-1.27,0) 5(1.27,0) 6(3.81,0) 7(6.35,0) 8(8.89,0)
  silkscreen extent -11.13,-1.32 10.41,1.32, body extent -10.51,-1.42 10.51,1.42, height 0.25
HRO_TYPE-C-31-M-12 [mm]
  rect 0.3x1.14 smd mask+0.05: A5(-1.25,4.75) A6(-0.25,4.75) A7(0.25,4.75) A8(1.25,4.75) B5(1.75,4.75) B6(0.75,4.75) B7(-0.75,4.75) B8(-1.75,4.75)
  rect 0.6x1.14 smd mask+0.05: GND(-3.2,4.75) GND(3.2,4.75) VBUS(-2.4,4.75) VBUS(2.4,4.75)
  oval 0.9x2 hole 0.6 slot 1.7 at 90 deg: SHIELD(-4.325,4.17) SHIELD(4.325,4.17)
  oval 0.9x1.7 hole 0.6 slot 1.4 at 90 deg: SHIELD(-4.325,0) SHIELD(4.325,0)
  round 0.6 hole 0.6 unplated: ""(-2.89,3.68) ""(2.89,3.68)
  silkscreen extent -4.47,-2.6 4.47,6.1, body extent -4.47,-2.6 4.47,5.31, height 3.31
INSE-MPU-6500-QFN24_M [mm] "QFN, 24-Leads, Body 3.1x3.1mm, Pitch 0.4mm, Thermal Pad 1.7X1.54mm, IPC Low Density"
  rect 0.6x0.2 smd: 1(-1.65,1) 6(-1.65,-1) 13(1.65,-1) 18(1.65,1)
  rect 0.9x0.2 smd: 2(-1.5,0.6) 3(-1.5,0.2) 4(-1.5,-0.2) 5(-1.5,-0.6) 14(1.5,-0.6) 15(1.5,-0.2) 16(1.5,0.2) 17(1.5,0.6)
  rect 0.2x0.6 smd: 7(-1,-1.65) 12(1,-1.65) 19(1,1.65) 24(-1,1.65)
  rect 0.2x0.9 smd: 8(-0.6,-1.5) 9(-0.2,-1.5) 10(0.2,-1.5) 11(0.6,-1.5) 20(0.6,1.5) 21(0.2,1.5) 22(-0.2,1.5) 23(-0.6,1.5)
  rect 1.7x1.54 smd: 25(0,0)
  Top Layer region: 1.95,1.1 1.95,0.9 1.05,0.9 1.25,1.1 1.95,1.1
  Top Layer region: 1.1,-1.95 0.9,-1.95 0.9,-1.05 1.1,-1.25 1.1,-1.95
  Top Layer region: -1.95,-1.1 -1.95,-0.9 -1.05,-0.9 -1.25,-1.1 -1.95,-1.1
  Top Layer region: -1.1,1.95 -0.9,1.95 -0.9,1.05 -1.1,1.25 -1.1,1.95
  Top Layer region: 1.1,1.95 0.9,1.95 0.9,1.05 1.1,1.25 1.1,1.95
  Top Layer region: 1.95,-1.1 1.95,-0.9 1.05,-0.9 1.25,-1.1 1.95,-1.1
  Top Layer region: -1.1,-1.95 -0.9,-1.95 -0.9,-1.05 -1.1,-1.25 -1.1,-1.95
  Top Layer region: -1.95,1.1 -1.95,0.9 -1.05,0.9 -1.25,1.1 -1.95,1.1
  silkscreen extent -2.47,-1.7 1.7,1.7, body extent -1.55,-1.55 1.55,1.55, height 0.95
JST-S2B-PH-K-S_V [mm] "THD, 2-Leads, Body 7.6x5.9mm, Pitch 2mm"
  rect 1.2x1.2 hole 0.7: 1(-1,2.45)
  round 1.2 hole 0.7: 2(1,2.45)
  silkscreen extent -2.95,-3.8 2.95,4.35, body extent -2.95,-3.8 2.95,3.8, height 4.8
QFP50P900X900X160-48N [mm]
  rect 1.56x0.28 smd: 1(-4.18,2.75) 2(-4.18,2.25) 3(-4.18,1.75) 4(-4.18,1.25) 5(-4.18,0.75) 6(-4.18,0.25) 7(-4.18,-0.25) 8(-4.18,-0.75) 9(-4.18,-1.25) 10(-4.18,-1.75) 11(-4.18,-2.25) 12(-4.18,-2.75) 25(4.18,-2.75) 26(4.18,-2.25) 27(4.18,-1.75) 28(4.18,-1.25) 29(4.18,-0.75) 30(4.18,-0.25) 31(4.18,0.25) 32(4.18,0.75) 33(4.18,1.25) 34(4.18,1.75) VDD(4.18,2.75) VSS(4.18,2.25)
  rect 0.28x1.56 smd: 13(-2.75,-4.18) 14(-2.25,-4.18) 15(-1.75,-4.18) 16(-1.25,-4.18) 17(-0.75,-4.18) 18(-0.25,-4.18) 19(0.25,-4.18) 20(0.75,-4.18) 21(1.25,-4.18) 22(1.75,-4.18) 37(2.75,4.18) 38(2.25,4.18) 39(1.75,4.18) 40(1.25,4.18) 41(0.75,4.18) 42(0.25,4.18) 43(-0.25,4.18) 44(-0.75,4.18) 45(-1.25,4.18) 46(-1.75,4.18) VDD(-2.75,4.18) VDD(2.75,-4.18) VSS(-2.25,4.18) VSS(2.25,-4.18)
  silkscreen extent -5.6,-3.5 3.5,3.5, body extent -4.5,-4.5 4.5,4.5, height 0.72
RESC0402(1005)_L [mm] "Chip Resistor, Body 1.0x0.5mm, IPC High Density"
  rrect25% 0.5x0.55 smd: 1(-0.45,0) 2(0.45,0)
  body extent -0.5,-0.25 0.5,0.25, height 0.3

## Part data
BAT1: library part CMP-1755-00004-1, "Male Header, Pitch 2 mm, 1 x 2 Position, Height 4.8 mm, Tail Length 3.4 mm, -25 to 85 degC, RoHS, Bulk", Capacitance="10 uF", Case\Package=Radial, LCSC Part #=C173752, Max Operating Temperature="85 degC", Min Operating Temperature="-40 degC", Package Quantity=200, Tolerance=20%, Voltage Rating="50 V"
BOOT0 RESET STM_PWR SW_BAT: library part CMP-1502-01068-4, "THT Vertical Pin Header WR-PHD, Pitch 2.54 mm, Single Row, 5 pins", Color=Black, Contact Resistance=20mΩ, Current Rating=3A, Max Operating Temperature=105°C, Min Operating Temperature=-40°C, Operating Supply Voltage=250V
C1 C2 C3 C5 C10 C11 C12 C13 C14: library part CMP-2000-05439-1, "Chip Capacitor, 100 nF, +/- 10%, 16 V, -55 to 125 degC, 0402 (1005 Metric), RoHS, Tape and Reel", Capacitance=100000pF, Case Size/Dimension=0402, Dielectric=X7R, LCSC Part #=C1525, Manufacturer="Samsung Electro-Mechanics", Rated Voltage=16V, Tolerance (%)=±10%
C4: library part CMP-001-00076-4, "Chip Capacitor, 4.7µF +/-20%, 10V, 0603, Thickness 1 mm", Case/Package=0603, LCSC Part #=C96446, Max Operating Temperature=85°C, Min Operating Temperature=-55°C, Tolerance=10%, Voltage Rating=10V
C6 C7 C8 C9: library part CMP-001-00076-4, "Chip Capacitor, 4.7µF +/-20%, 10V, 0603, Thickness 1 mm", Case/Package=0603, LCSC Part #=C19666, Max Operating Temperature=85°C, Min Operating Temperature=-55°C, Tolerance=10%, Voltage Rating=10V
CHG: library part CMP-2000-05496-1, "LED Yellow , 60 mW, 25 mA, -40 to 85 degC, 2-Pin SMD, RoHS, Tape and Reel  0805", Color=Yellow/Green, Forward (Drive) Current=25mA, Forward Voltage=2V, LCSC Part #=C2296, Manufacturer="Everlight Electronics", Package Description="2-Pin Surface Mount Device, Body 2 x 1.25 mm", Package Reference=17-21SYGC
D1 D2 D3 D4 D5 D6 D7 D8 D9 D10 D11 D12 D13 D14 D15 D16 D17 D18 D19 D20 D21 D22 D23 D24 D25 D26 D27 D28 D29 D30 D31 D32 D33 D34 D35 D36 D37 D38 D39 D40 D41 D42 D43 D44 D45 D46 D47 D48 D49 D50 D51 D52 D53 D54 D55 D56 D57 D58 D59 D60 D61 D62 D63 D64 D65 D66 D67 D68 D69 D70 D71 D72 D73 D74 D75 D76 D77 D78 D79 D80 D81 D82 D83 D84 D85 D86 D87 D88 D89 D90 D91 D92 D93 D94 D95 D96 D97 D98 D99 D100 D101 D102 D103 D104 D105 D106 D107 D108 D109 D110 D111 D112 D113 D114 D115 D116 D117 D118 D119 D120 D121 D122 D123 D124 D125 D126 D127 D128 D129 D130 D131 D132 D133 D134 D135 D136 D137 D138 D139 D140 D141 D142 D143 D144 D145 D146 D147 D148 D149 D150 D151 D152 D153 D154 D155 D156 D157 D158 D159 D160 D161 D162 D163 D164 D165 D166 D167 D168 D169 D170 D171 D172 D173 D174 D175 D176 D177 D178 D179 D180 D181 D182 D183 D184 D185 D186 D187 D188 D189 D190 D191 D192 D193 D194 D195 D196 D197 D198 D199 D200 D201 D202 D203 D204 D205 D206 D207 D208 D209 D210 D211 D212 D213 D214 D215 D216 D217 D218 D219 D220 D221 D222 D223 D224 D225 D226 D227 D228 D229 D230 D231 D232 D233 D234 D235 D236 D237 D238 D239 D240: library part CMP-007-00000-2, "Chip LED, Blue , 5 V, 10 mA, 30 mW, -40 to 85 degC, 2-Pin SMD (0402), RoHS, Tape and Reel", Case/Package=0402, Forward Current=5mA, Forward Voltage=2.6V, Illumination Colour=White, LCSC Part #=C22355736, Manufacturer="Everlight Electronics", Max Operating Temperature=85°C, Min Operating Temperature=-40°C, Package Description="2-Pin Surface Mount Device, Body 1 x 0.5 mm", Package Quantity=3000, Power=30mW
J1 J2 J3 J4 J5 J6: library part CMP-15831-000033-1, "CONN HEADER VERT 8POS 2.54MM", Case/Package=SIL, Color=Black, Contact Resistance=30mR, Current Rating=3A, Insulation Resistance=1GR, LCSC Part #=C492407, Max Operating Temperature=105°C, Min Operating Temperature=-40°C, Package Quantity=1000
LED: library part CMP-2000-05496-1, "LED Red , 60 mW, 25 mA, -40 to 85 degC, 2-Pin SMD, RoHS, Tape and Reel  0805", Color=Yellow/Green, Forward (Drive) Current=25mA, Forward Voltage=2V, LCSC Part #=C84256, Manufacturer="Everlight Electronics", Package Description="2-Pin Surface Mount Device, Body 2 x 1.25 mm", Package Reference=17-21SYGC
PWR: library part CMP-2000-05496-1, "LED Green, 60 mW, 25 mA, -40 to 85 degC, 2-Pin SMD, RoHS, Tape and Reel  0805", Color=Yellow/Green, Forward (Drive) Current=25mA, Forward Voltage=2V, LCSC Part #=C2297, Manufacturer="Everlight Electronics", Package Description="2-Pin Surface Mount Device, Body 2 x 1.25 mm", Package Reference=17-21SYGC
PWR_IN1: "USB Connectors 24 Receptacle 1 8.94*7.3mm RoHS", LCSC Part #=C165948, Package=Package
R1 R8: library part CMP-009-00147-3, "Chip Resistor, 6,2 kOhms, +/-5 %, 63 mW, -55 to 155 degC, 0402", Case/Package=0402, LCSC Part #=C25752, Max Operating Temperature=155°C, Min Operating Temperature=-55°C, Power=63mW, Tolerance=5%
R2: library part CMP-009-00147-3, "Chip Resistor, 6,2 kOhms, +/-5 %, 63 mW, -55 to 155 degC, 0402", Case/Package=0402, LCSC Part #=C4109, Max Operating Temperature=155°C, Min Operating Temperature=-55°C, Power=63mW, Tolerance=5%
R3 R5 R7: library part CMP-009-00147-3, "Chip Resistor, 6,2 kOhms, +/-5 %, 63 mW, -55 to 155 degC, 0402", Case/Package=0402, LCSC Part #=C25867, Max Operating Temperature=155°C, Min Operating Temperature=-55°C, Power=63mW, Tolerance=5%
R4 R6: library part CMP-009-00147-3, "Chip Resistor, 6,2 kOhms, +/-5 %, 63 mW, -55 to 155 degC, 0402", Case/Package=0402, LCSC Part #=C25905, Max Operating Temperature=155°C, Min Operating Temperature=-55°C, Power=63mW, Tolerance=5%
U1: library part CMP-0133-00138-2, "IC LI-ION/LI-POLY CTRLR SOT23-5", Case/Package=SOT-23, LCSC Part #=C38066, Max Charge Current=500mA, Max Input Voltage=6V, Max Operating Temperature=85°C, Max Output Voltage=4.5V, Max Power Dissipation=1.54W, Min Operating Temperature=-40°C, Min Output Voltage=4.168V, Min Supply Voltage=3.75V, Output Current=10mA, Output Voltage=4.2V, Package Quantity=3000
U2: library part CMP-04917-000286-1, "IC REG LINEAR 3.3V 200MA SOT23-5", LCSC Part #=C2887324
U3: "ARMÂ® CortexÂ®-M4 STM32L4 Microcontroller IC 32-Bit Single-Core 80MHz 256KB (256K x 8) FLASH 48-LQFP (7x7)", LCSC Part #=C486681, Package="LQFP-48 STMicroelectronics"
U4: library part CMP-2000-05154-1, "3-Axis Gyroscope and 3-Axis Accelerometer Motion Processing Unit with I2C and SPI, 1.71 to 3.45 V, -40 to 85 degC, 24-Pin QFN, RoHS, Tape and Reel", LCSC Part #=C50278, Manufacturer=InvenSense, Standard Package=1

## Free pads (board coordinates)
  round 1.524 hole 0.762: 2(2.261,3.277) 2(35.281,3.277) 2(35.281,43.612) 3(2.261,43.612) 4(40.716,43.612) 5(73.762,43.612) 6(73.762,3.277) 7(40.716,3.302)
  round 1.152 hole 1.152 unplated mask+0: 2(37.922,3.277) 2(37.922,43.637) 2(71.501,43.561) 2(71.552,3.15)

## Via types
v1: diameter 0.813, hole 0.406, Top Layer to Bottom Layer, 241 vias
v2: diameter 1, hole 0.5, Top Layer to Bottom Layer, 55 vias
v3: diameter 0.5, hole 0.2, Top Layer to Bottom Layer, 4 vias

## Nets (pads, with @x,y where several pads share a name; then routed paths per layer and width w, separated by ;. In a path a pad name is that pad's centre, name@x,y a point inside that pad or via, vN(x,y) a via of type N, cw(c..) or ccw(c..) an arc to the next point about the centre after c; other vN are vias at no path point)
CC1: PWR_IN1.A5 R4.2 | length 2
  Top Layer w0.3: PWR_IN1.A5@7.674,24.612 9.618,24.612 R4.2@9.659,24.653
CC2: PWR_IN1.B5 R6.2 | length 2
  Top Layer w0.3: PWR_IN1.B5@7.674,21.612 9.628,21.612 R6.2@9.659,21.643
GND: BAT1.2 BOOT0.4 C1.1 C2.1 C3.1 C4.1 C5.1 C6.1 C7.1 C8.1 C9.1 C10.1 C11.1 C12.1 C13.1 C14.1 J1.1 J1.2 J1.3 PWR_IN1.GND PWR_IN1.SHIELD R2.1 R4.1 R5.1 R6.1 RESET.3 U1.2 U2.2 U2.4 U3.8 U3.VSS U4.11 U4.18 U4.20 U4.25 | length 80.9
  Top Layer w0.2: U4.20@19.643,12.996 20.543,12.996 v3(20.643,12.896) ; U4.18@20.143,14.046 20.143,14.989 20.699,15.545 C14.1@20.719,15.545 ; v3(21.643,12.896) 21.743,12.996 U4.11@22.643,12.996 23.217,12.996 24.071,13.85 24.327,13.85 24.587,14.11 C10.1@24.587,14.13
  Top Layer w0.3: PWR_IN1.GND@7.674,20.162 9.652,20.162 ; v2(8.585,9.5) C8.1@12.889,9.5 12.889,10.657 12.639,10.907 U2.4@12.639,11.447 12.639,11.84 U2.4@12.765,11.966 ; v2(8.966,36.551) 9.1,36.417 9.507,36.417 10.121,35.802 10.121,35.334 C7.1@10.262,35.193 ; 9.659,20.155 9.652,20.162 ; C7.1@10.311,35.193 10.492,35.013 10.492,34.963 10.697,34.757 U1.2@12.852,34.757 ; R4.1@10.559,24.653 10.559,23.148 ; C5.1@12.675,23.139 10.568,23.139 10.559,23.148 ; R5.1@13.455,17.247 13.453,17.245 13.453,15.75 C9.1@13.451,15.748 13.589,15.61 U2.2@13.589,13.648 ; R5.1@13.455,17.298 R5.1@13.455,17.323 14.107,17.323 14.554,16.875 v2(14.554,16.713) ; C6.1@15.088,29.602 15.095,29.609 17.911,29.609 C4.1@17.918,29.616 ; v2(17.297,32.741) 17.297,32.639 17.918,32.018 C4.1@17.918,29.616 ; R2.1@17.323,36.62 19.632,36.62 19.888,36.363 v2(19.888,34.95) ; v2(17.45,23.266) 17.484,23.232 18.688,23.232 18.702,23.246 18.702,23.373 19.108,22.968 19.655,22.968 19.907,22.716 U3.8@21.231,22.716 ; v2(17.907,15.596) ccw(c18.074,15.845) 18.073,15.545 C14.1@20.719,15.545 ; C13.1@17.925,26.238 17.922,26.242 17.922,29.613 C4.1@17.918,29.616 ; v2(20.168,32.106) 20.895,31.378 21.657,31.378 22.428,30.607 22.428,29.807 22.769,29.466 23.161,29.466 U3.VSS@23.161,28.276 ; v2(22.555,9.474) 24.479,9.474 C11.1@24.689,9.467 ; U3.VSS@27.661,19.286 27.661,14.097 28.194,13.564 v2(29.464,13.564) 29.408,13.62 29.408,17.47 C2.1@29.352,17.526 ; U3.VSS@29.591,25.716 31.362,25.716 C12.1@31.572,25.926 31.572,25.946 31.782,26.156 32.082,26.156 32.258,26.332 32.258,27.678 31.877,28.06 31.877,28.753 v2(31.852,28.778) ; 9.652,20.162 10.547,20.162 10.559,20.175 R6.1@10.559,21.643 10.559,23.148
  Bottom Layer w0.3: v2(8.585,9.5) 8.585,9.689 8.966,10.07 BAT1.2@8.966,12.243
  other v3: 20.643,11.896 21.643,11.896
LED_CHG_K: CHG.2 R3.2 | length 2.6
  Top Layer w0.3: CHG.2@12.107,26.289 12.557,26.739 R3.2@12.557,28.7
MPU_CS: U3.15 U4.22 | length 10.9
  Top Layer w0.2: v2(18.872,14.783) 18.872,12.313 18.989,12.196 U4.22@19.643,12.196
  Top Layer w0.3: v2(22.909,16.866) 23.043,17 23.043,17.438 23.661,18.056 U3.15@23.661,19.286
  Bottom Layer w0.3: v2(18.872,14.783) 20.827,14.783 v2(22.909,16.866)
MPU_INT: U3.14 U4.12 | length 8
  Top Layer w0.2: U4.12@22.793,13.396 22.993,13.396 24.027,14.43 24.027,14.886 23.684,15.229 23.684,15.724 23.243,16.166 22.619,16.166 22.209,16.576 22.209,17.156 23.161,18.107 U3.14@23.161,19.286
MPU_MISO: U3.16 U4.9 | length 10.1
  Top Layer w0.2: U4.9@22.643,12.196 24.062,12.196 24.371,11.887 v2(24.587,11.887)
  Top Layer w0.3: U3.16@24.161,19.286 24.161,17.843 23.659,17.342 23.659,16.244 v2(24.384,15.519)
  Bottom Layer w0.3: v2(24.384,15.519) 24.486,15.418 24.486,11.989 v2(24.587,11.887)
MPU_MOSI: U3.17 U4.24 | length 14.5
  Top Layer w0.2: v2(18.669,9.83) 18.669,11.152 18.913,11.397 U4.24@19.543,11.397
  Top Layer w0.3: v2(24.409,16.84) 24.409,17.03 24.661,17.281 U3.17@24.661,19.286
  Bottom Layer w0.3: v2(18.669,9.83) 20.139,11.3 20.139,13.105 21.94,14.906 22.475,14.906 v2(24.409,16.84)
MPU_REGOUT: C10.2 U4.10 | length 2.2
  Top Layer w0.2: U4.10@22.643,12.596 24.054,12.596 24.587,13.13 C10.2@24.587,13.15
MPU_SCLK: U3.11 U4.23 | length 14.8
  Top Layer w0.2: v2@18.099,11.797 U4.23@19.693,11.797
  Top Layer w0.3: v2(16.256,15.57) 16.256,17.45 16.586,17.78 16.586,17.983 19.819,21.216 U3.11@21.231,21.216
  Bottom Layer w0.3: v2(16.256,15.57) 16.968,14.858 17.317,14.858 18.085,14.091 v2(18.085,11.811)
NetBOOT0_3: BOOT0.3 R8.1 | length 13.1
  Top Layer w0.3: R8.1@24.384,33.488 24.397,33.501 24.397,34.785 v2(24.409,34.798)
  Bottom Layer w0.3: v2(24.409,34.798) 25.178,34.03 31.276,34.03 32.106,33.2 32.106,31.824 32.281,31.648 BOOT0.3@34.061,31.648
PB0: J3.1 U3.18 | length 63.8
  Top Layer w0.3: U3.18@25.161,19.286 25.161,15.999 25.461,15.699 25.461,13.146 25.729,12.879 25.729,10.136 v2(25.832,10.033)
  Bottom Layer w0.3: J3.1@9.601,43.332 6.481,43.332 6.306,43.157 6.306,30.27 8.865,27.711 8.865,17.803 9.04,17.628 25.529,17.628 25.729,17.428 25.729,10.136 v2(25.832,10.033)
PB1: J3.2 U3.19 | length 63.3
  Top Layer w0.3: U3.19@25.661,19.286 25.661,16.065 25.861,15.865 25.861,13.312 26.479,12.694 v2(26.479,11.107)
  Bottom Layer w0.3: J3.2@12.141,43.332 10.897,42.088 6.958,42.088 6.782,41.912 6.782,30.36 9.296,27.845 9.296,18.235 9.472,18.059 26.293,18.059 26.479,17.873 v2(26.479,11.107)
PB2: J3.3 U3.20 | length 68.4
  Top Layer w0.3: U3.20@26.161,19.286 26.161,16.131 26.261,16.031 26.261,13.552 27.229,12.585 27.229,9.826 v2(27.138,9.735)
  Bottom Layer w0.3: J3.3@14.681,43.332 13.037,41.688 7.389,41.688 7.214,41.512 7.214,30.494 9.696,28.011 9.696,18.718 9.911,18.503 27.053,18.503 27.229,18.327 27.229,9.826 v2(27.138,9.735)
PB3: J3.4 U3.39 | length 38.8
  Top Layer w0.3: J3.4@17.221,43.332 18.847,44.958 32.565,44.958 32.741,44.782 32.741,32.181 32.565,32.005 27.364,32.005 27.161,31.803 U3.39@27.161,27.646
PB4: J3.5 U3.40 | length 35.4
  Top Layer w0.3: J3.5@19.761,43.332 20.987,44.558 32.158,44.558 32.336,44.381 32.336,32.689 32.158,32.512 26.837,32.512 26.661,32.336 U3.40@26.661,27.646
PB5: J3.6 U3.41 | length 29.7
  Top Layer w0.3: U3.41@26.161,27.646 26.161,32.844 26.337,33.02 31.396,33.02 31.572,33.196 31.572,41.033 v2(31.586,41.046)
  Bottom Layer w0.3: J3.6@22.301,43.332 22.301,41.832 22.477,41.656 30.852,41.656 31.461,41.046 v2(31.586,41.046)
PB6: J3.7 U3.42 | length 28.2
  Top Layer w0.3: U3.42@25.661,27.646 25.661,33.301 25.837,33.477 30.621,33.477 31.115,33.971 31.115,40.183 30.836,40.462 30.836,42.316 v2(31.471,42.951)
  Bottom Layer w0.3: J3.7@24.841,43.332 26.056,42.117 30.637,42.117 v2(31.471,42.951)
PB7: J3.8 U3.43 | length 24
  Top Layer w0.3: U3.43@25.161,27.646 25.161,33.759 25.337,33.934 30.507,33.934 30.683,34.11 30.683,39.776 30.328,40.132 30.328,43.131 30.126,43.332 J3.8@27.381,43.332
PB8: J2.1 U3.45 | length 69.4
  Top Layer w0.3: v2(21.59,33.553) 21.59,33.528 22.549,32.569 23.235,32.569 24.161,31.643 U3.45@24.161,27.646
  Bottom Layer w0.3: J2.1@9.601,3.581 11.22,1.962 30.863,1.962 31.065,2.164 31.065,28.504 30.328,29.242 30.328,32.463 29.161,33.63 21.666,33.63 v2(21.59,33.553)
PB9: J2.2 U3.46 | length 63.1
  Top Layer w0.3: v2(21.641,32.207) 22.449,31.399 22.961,31.399 23.661,30.699 U3.46@23.661,27.646
  Bottom Layer w0.3: J2.2@12.141,3.581 13.36,2.362 30.253,2.362 30.665,2.774 30.665,28.339 29.87,29.133 29.87,31.768 29.633,32.005 23.888,32.005 23.267,31.385 22.463,31.385 v2(21.641,32.207)
PB10: J2.3 U3.21 | length 28.9
  Top Layer w0.3: U3.21@26.661,19.286 26.661,13.718 27.979,12.4 v2(27.979,10.719)
  Bottom Layer w0.3: J2.3@14.681,3.581 16.586,5.486 27.776,5.486 28.596,6.306 28.596,8.569 27.915,9.25 27.915,10.655 v2(27.979,10.719)
PB11: J2.4 U3.22 | length 28.9
  Top Layer w0.3: U3.22@27.161,19.286 27.161,13.784 28.729,12.216 28.729,9.679 v2(28.702,9.652)
  Bottom Layer w0.3: J2.4@17.221,3.581 18.642,5.002 29.741,5.002 30.265,5.525 30.265,8.089 v2(28.702,9.652)
PB12: J2.5 U3.25 | length 27.2
  Top Layer w0.3: J2.5@19.761,3.581 21.975,5.795 30.279,5.795 30.455,5.971 30.455,20.54 30.279,20.716 U3.25@29.591,20.716
PB13: J2.6 U3.26 | length 26.7
  Top Layer w0.3: J2.6@22.301,3.581 23.946,5.226 30.863,5.226 31.039,5.402 31.039,21.04 30.863,21.216 U3.26@29.591,21.216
